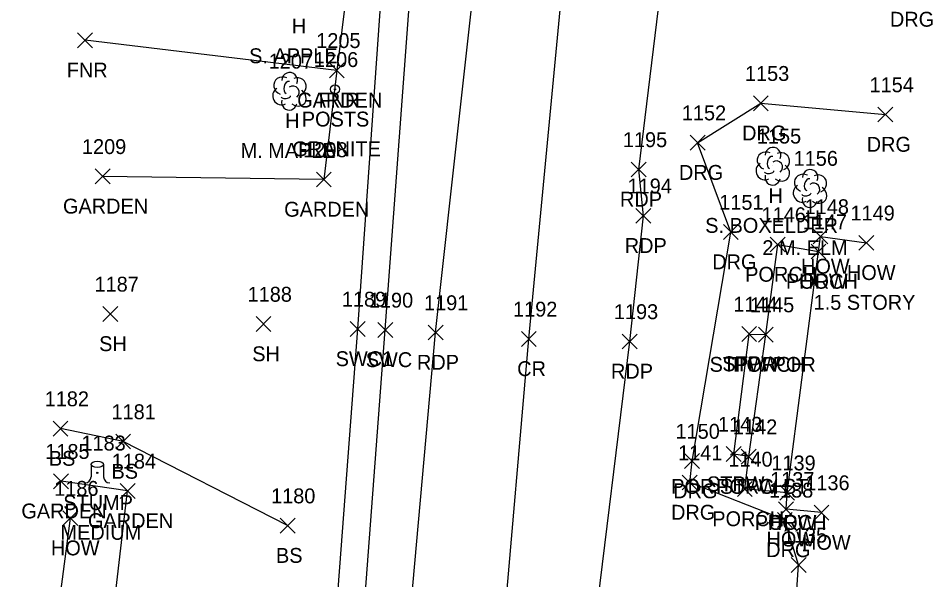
# Model space of a CAD drawing. Extents: x 1653908 to 1654393, y 539913 to 544256.
# Drawn here: x 1653960.4 to 1654083.2, y 541216.3 to 541291.8 of the extents above; entities that cross this region are included whole.
import ezdxf

# ---------------------------------------------------------------- set-up
doc = ezdxf.new("R2010")
doc.units = 0
for name, color, linetype in [('L_A', 7, 'Continuous'), ('L_C', 7, 'Continuous'), ('L_I', 7, 'Continuous'), ('L_TIC', 7, 'Continuous'), ('LAPB', 7, 'Continuous'), ('LBC', 7, 'Continuous'), ('LBF', 7, 'Continuous'), ('LELB', 7, 'Continuous'), ('LFNC', 7, 'Continuous'), ('LPST', 7, 'Continuous'), ('LTD', 7, 'Continuous'), ('LTS', 7, 'Continuous'), ('P_A', 7, 'Continuous'), ('P_I', 7, 'Continuous'), ('P_TIC', 7, 'Continuous'), ('PET', 7, 'Continuous'), ('PRC', 7, 'Continuous'), ('R_A', 7, 'Continuous'), ('R_I', 7, 'Continuous'), ('R_TIC', 7, 'Continuous'), ('RDG', 7, 'Continuous'), ('RSW', 7, 'Continuous')]:
    doc.layers.add(name, color=color, linetype=linetype)

msp = doc.modelspace()

# ---------------------------------------------------------------- linework, layer by layer
at = {"layer": 'L_TIC'}
for points in [[(1653968.35, 541287.8), (1653970.35, 541289.8)], [(1653970.35, 541287.8), (1653968.35, 541289.8)], [(1654002.18, 541283.76), (1654004.18, 541285.76)], [(1654004.18, 541283.76), (1654002.18, 541285.76)], [(1654002.18, 541283.76), (1654004.18, 541285.76)], [(1654004.18, 541283.76), (1654002.18, 541285.76)], [(1653970.71, 541269.51), (1653972.71, 541271.51)], [(1653972.71, 541269.51), (1653970.71, 541271.51)], [(1654000.43, 541269.09), (1654002.43, 541271.09)], [(1654002.43, 541269.09), (1654000.43, 541271.09)], [(1654061.42, 541260.35), (1654063.42, 541262.35)], [(1654063.42, 541260.35), (1654061.42, 541262.35)], [(1654067.16, 541261.43), (1654069.16, 541263.43)], [(1654069.16, 541261.43), (1654067.16, 541263.43)], [(1654073.32, 541260.58), (1654075.32, 541262.58)], [(1654075.32, 541260.58), (1654073.32, 541262.58)], [(1654066.9, 541259.41), (1654068.9, 541261.41)], [(1654068.9, 541259.41), (1654066.9, 541261.41)], [(1654066.9, 541259.41), (1654068.9, 541261.41)], [(1654068.9, 541259.41), (1654066.9, 541261.41)], [(1653971.75, 541251.02), (1653973.75, 541253.02)], [(1653973.75, 541251.02), (1653971.75, 541253.02)], [(1653992.32, 541249.66), (1653994.32, 541251.66)], [(1653994.32, 541249.66), (1653992.32, 541251.66)], [(1654057.57, 541248.32), (1654059.57, 541250.32)], [(1654059.57, 541248.32), (1654057.57, 541250.32)], [(1654059.81, 541248.24), (1654061.81, 541250.24)], [(1654061.81, 541248.24), (1654059.81, 541250.24)], [(1654059.81, 541248.24), (1654061.81, 541250.24)], [(1654061.81, 541248.24), (1654059.81, 541250.24)], [(1653965.04, 541235.61), (1653967.04, 541237.61)], [(1653967.04, 541235.61), (1653965.04, 541237.61)], [(1653973.46, 541233.87), (1653975.46, 541235.87)], [(1653975.46, 541233.87), (1653973.46, 541235.87)], [(1654055.5, 541232.18), (1654057.5, 541234.18)], [(1654057.5, 541232.18), (1654055.5, 541234.18)], [(1654057.52, 541231.84), (1654059.52, 541233.84)], [(1654059.52, 541231.84), (1654057.52, 541233.84)], [(1654057.52, 541231.84), (1654059.52, 541233.84)], [(1654059.52, 541231.84), (1654057.52, 541233.84)], [(1653965.12, 541228.53), (1653967.12, 541230.53)], [(1653967.12, 541228.53), (1653965.12, 541230.53)], [(1653974.07, 541227.23), (1653976.07, 541229.23)], [(1653976.07, 541227.23), (1653974.07, 541229.23)], [(1654056.99, 541227.49), (1654058.99, 541229.49)], [(1654058.99, 541227.49), (1654056.99, 541229.49)], [(1654062.69, 541226.99), (1654064.69, 541228.99)], [(1654064.69, 541226.99), (1654062.69, 541228.99)], [(1654062.69, 541226.99), (1654064.69, 541228.99)], [(1654064.69, 541226.99), (1654062.69, 541228.99)], [(1654062.53, 541224.76), (1654064.53, 541226.76)], [(1654064.53, 541224.76), (1654062.53, 541226.76)], [(1653966.38, 541223.57), (1653968.38, 541225.57)], [(1653968.38, 541223.57), (1653966.38, 541225.57)], [(1654067.3, 541224.32), (1654069.3, 541226.32)], [(1654069.3, 541224.32), (1654067.3, 541226.32)], [(1653995.56, 541222.56), (1653997.56, 541224.56)], [(1653997.56, 541222.56), (1653995.56, 541224.56)]]:
    msp.add_lwpolyline(points, dxfattribs=at)
at = {"layer": 'LAPB'}
for points in [[(1654003.18, 541284.76), (1654001.43, 541270.09), (1653971.71, 541270.51)], [(1653972.26, 541204.38), (1653975.07, 541228.23), (1653966.12, 541229.53)]]:
    msp.add_lwpolyline(points, dxfattribs=at)
at = {"layer": 'LBC'}
for points in [[(1654068.3, 541225.32), (1654063.53, 541225.76), (1654063.69, 541227.99), (1654067.9, 541260.41), (1654068.16, 541262.43), (1654074.32, 541261.58)], [(1653960.38, 541198.85), (1653963.61, 541198.2), (1653964.17, 541200.25), (1653965.17, 541207.51), (1653967.38, 541224.57)]]:
    msp.add_lwpolyline(points, dxfattribs=at)
at = {"layer": 'LBF'}
for points in [[(1654063.69, 541227.99), (1654057.99, 541228.49), (1654058.52, 541232.84), (1654060.81, 541249.24), (1654062.42, 541261.35), (1654067.9, 541260.41)], [(1654058.52, 541232.84), (1654056.5, 541233.18), (1654058.57, 541249.32), (1654060.81, 541249.24)]]:
    msp.add_lwpolyline(points, dxfattribs=at)
at = {"layer": 'LELB'}
msp.add_lwpolyline([(1653996.56, 541223.56), (1653974.46, 541234.87), (1653966.04, 541236.61)], dxfattribs=at)
at = {"layer": 'LFNC'}
msp.add_lwpolyline([(1654006.47, 541311.55), (1654003.18, 541284.76), (1653969.35, 541288.8)], dxfattribs=at)
at = {"layer": 'LPST'}
for radius in [0.625, 0.0833]:
    msp.add_circle((1654002.93, 541282.21), radius, dxfattribs=at)
at = {"layer": 'LTD'}
for p, q in [((1653996.79, 541282), (1653996.79, 541282)), ((1653996.79, 541282), (1653996.79, 541282)), ((1654061.74, 541271.92), (1654061.74, 541271.92)), ((1654061.74, 541271.92), (1654061.74, 541271.92)), ((1654066.73, 541268.93), (1654066.73, 541268.93)), ((1654066.73, 541268.93), (1654066.73, 541268.93))]:
    msp.add_line(p, q, dxfattribs=at)
for centre in [(1653996.84, 541283.43), (1654061.78, 541273.36), (1654066.78, 541270.37)]:
    msp.add_arc(centre, 1.05, 335.5272, 180.9563, dxfattribs=at)
for centre, major_axis, ratio, start_param, end_param in [((1653996, 541282.66), (1.21, -0.51), 0.895232, 1.570796, 4.712389), ((1653996.59, 541282.46), (-0.208, -0.792), 0.645439, 3.141593, 6.283185), ((1653997.84, 541282.58), (-1.14, -0.48), 0.949671, 1.570796, 4.712389), ((1653995.71, 541281.29), (0.58, -1.04), 0.959034, 3.141593, 6.283185), ((1653997.29, 541281.83), (-0.5, 0.667), 0.989748, 3.141593, 6.283185), ((1653997.79, 541281.16), (-1.09, 0.79), 0.841452, 1.570796, 4.712389), ((1653996.34, 541281.25), (-0.625, -0.083), 0.423636, 0, 3.141593), ((1653996.79, 541280.5), (0.26, 1.06), 0.942809, 1.570796, 4.712389), ((1654060.95, 541272.59), (1.21, -0.51), 0.895232, 1.570796, 4.712389), ((1654062.78, 541272.51), (-1.14, -0.48), 0.949671, 1.570796, 4.712389), ((1654060.65, 541271.22), (0.58, -1.04), 0.959034, 3.141593, 6.283185), ((1654061.53, 541272.38), (-0.208, -0.792), 0.645439, 3.141593, 6.283185), ((1654062.24, 541271.76), (-0.5, 0.667), 0.989748, 3.141593, 6.283185), ((1654061.28, 541271.17), (-0.625, -0.083), 0.423636, 0, 3.141593), ((1654062.74, 541271.09), (-1.09, 0.79), 0.841452, 1.570796, 4.712389), ((1654065.94, 541269.6), (1.21, -0.51), 0.895232, 1.570796, 4.712389), ((1654061.74, 541270.42), (0.26, 1.06), 0.942809, 1.570796, 4.712389), ((1654066.52, 541269.39), (-0.208, -0.792), 0.645439, 3.141593, 6.283185), ((1654067.23, 541268.77), (-0.5, 0.667), 0.989748, 3.141593, 6.283185), ((1654067.77, 541269.52), (-1.14, -0.48), 0.949671, 1.570796, 4.712389), ((1654065.65, 541268.23), (0.58, -1.04), 0.959034, 3.141593, 6.283185), ((1654067.73, 541268.1), (-1.09, 0.79), 0.841452, 1.570796, 4.712389), ((1654066.73, 541267.43), (0.26, 1.06), 0.942809, 1.570796, 4.712389), ((1654066.27, 541268.18), (-0.625, -0.083), 0.423636, 0, 3.141593)]:
    msp.add_ellipse(centre, major_axis=major_axis, ratio=ratio, start_param=start_param, end_param=end_param, dxfattribs=at)
at = {"layer": 'LTS'}
for p, q in [((1653970.16, 541231.8), (1653970.16, 541230.13)), ((1653971.83, 541231.63), (1653971.83, 541231.8)), ((1653971.83, 541231.8), (1653971.83, 541230.13)), ((1653970.99, 541230.66), (1653970.99, 541230.66)), ((1653970.99, 541230.66), (1653970.99, 541230.66)), ((1653970.99, 541230.63), (1653970.99, 541230.63))]:
    msp.add_line(p, q, dxfattribs=at)
msp.add_circle((1653970.99, 541230.66), 0.0833, dxfattribs=at)
for centre, start, end in [((1653969.33, 541230.13), 270, 360), ((1653972.66, 541230.13), 180, 270)]:
    msp.add_arc(centre, 0.833, start, end, dxfattribs=at)
msp.add_ellipse((1653970.99, 541231.8), major_axis=(-0.833, 0), ratio=0.5, dxfattribs=at)
at = {"layer": 'P_TIC'}
for points in [[(1654042.73, 541270.44), (1654044.73, 541272.44)], [(1654044.73, 541270.44), (1654042.73, 541272.44)], [(1654043.37, 541264.21), (1654045.37, 541266.21)], [(1654045.37, 541264.21), (1654043.37, 541266.21)], [(1654015.45, 541248.52), (1654017.45, 541250.52)], [(1654017.45, 541248.52), (1654015.45, 541250.52)], [(1654027.97, 541247.66), (1654029.97, 541249.66)], [(1654029.97, 541247.66), (1654027.97, 541249.66)], [(1654041.53, 541247.32), (1654043.53, 541249.32)], [(1654043.53, 541247.32), (1654041.53, 541249.32)]]:
    msp.add_lwpolyline(points, dxfattribs=at)
at = {"layer": 'PET'}
for points in [[(1654002.71, 541022.85), (1654002.8, 541044.57), (1654003.39, 541071.89), (1654004.24, 541078.69), (1654006.74, 541130.14), (1654008.35, 541153.98), (1654010.07, 541183.44), (1654012.88, 541209.94), (1654016.45, 541249.52), (1654022.91, 541308.12), (1654024.64, 541328.52), (1654031.79, 541410), (1654035.81, 541442.82), (1654037.01, 541460.37), (1654040.04, 541491.49), (1654045.58, 541525.89), (1654049.59, 541568.11), (1654053.33, 541590.16), (1654054.27, 541598.35), (1654062.59, 541587.52), (1654071.87, 541577.06), (1654070.19, 541559.91), (1654067.66, 541531.5), (1654064.32, 541497.28)], [(1654026.62, 541021.77), (1654028.54, 541070.24), (1654031.49, 541127.98), (1654037.66, 541208.54), (1654042.53, 541248.32), (1654044.37, 541265.21), (1654043.73, 541271.44), (1654047, 541298.33), (1654052.52, 541346.47), (1654054.45, 541365.83), (1654058.25, 541433.29), (1654064.32, 541497.28)]]:
    msp.add_lwpolyline(points, dxfattribs=at)
at = {"layer": 'PRC'}
msp.add_lwpolyline([(1654015.22, 541022.42), (1654016.68, 541078.09), (1654019.78, 541129.03), (1654023.08, 541180.04), (1654025.54, 541208.79), (1654028.97, 541248.66), (1654033.81, 541299.54), (1654044.55, 541409.64), (1654048.4, 541449.61), (1654049.07, 541458.74), (1654052.54, 541493.4), (1654055.94, 541523.17), (1654060.18, 541564.47), (1654062.59, 541587.52)], dxfattribs=at)
at = {"layer": 'R_TIC'}
for points in [[(1654059.14, 541279.34), (1654061.14, 541281.34)], [(1654061.14, 541279.34), (1654059.14, 541281.34)], [(1654075.88, 541277.82), (1654077.88, 541279.82)], [(1654077.88, 541277.82), (1654075.88, 541279.82)], [(1654050.65, 541274.04), (1654052.65, 541276.04)], [(1654052.65, 541274.04), (1654050.65, 541276.04)], [(1654055.12, 541262.02), (1654057.12, 541264.02)], [(1654057.12, 541262.02), (1654055.12, 541264.02)], [(1654004.98, 541249), (1654006.98, 541251)], [(1654006.98, 541249), (1654004.98, 541251)], [(1654008.69, 541248.87), (1654010.69, 541250.87)], [(1654010.69, 541248.87), (1654008.69, 541250.87)], [(1654049.9, 541231.24), (1654051.9, 541233.24)], [(1654051.9, 541231.24), (1654049.9, 541233.24)], [(1654049.59, 541228.36), (1654051.59, 541230.36)], [(1654051.59, 541228.36), (1654049.59, 541230.36)], [(1654062.37, 541223.33), (1654064.37, 541225.33)], [(1654064.37, 541223.33), (1654062.37, 541225.33)], [(1654064.22, 541217.28), (1654066.22, 541219.28)], [(1654066.22, 541217.28), (1654064.22, 541219.28)]]:
    msp.add_lwpolyline(points, dxfattribs=at)
at = {"layer": 'RDG'}
msp.add_lwpolyline([(1654028.54, 541070.24), (1654038.6, 541077.25), (1654059.57, 541076.94), (1654061.03, 541094.58), (1654044.02, 541099.01), (1654043.13, 541126.19), (1654037.88, 541140.53), (1654039.43, 541148.38), (1654055.52, 541147.43), (1654059.02, 541158.08), (1654052.9, 541167.53), (1654052.51, 541181.31), (1654043.29, 541183.51), (1654044.31, 541207.87), (1654064.52, 541208.31), (1654065.22, 541218.28), (1654063.37, 541224.33), (1654050.59, 541229.36), (1654050.9, 541232.24), (1654056.12, 541263.02), (1654051.65, 541275.04), (1654060.14, 541280.34), (1654076.88, 541278.82)], dxfattribs=at)
at = {"layer": 'RSW'}
for points in [[(1653995.61, 541066.36), (1653991.56, 541066.06), (1653992.58, 541078.58), (1653996.53, 541130.67), (1653999, 541158.35), (1654000.18, 541180.99), (1654002.98, 541210.26), (1654005.98, 541250), (1654010.23, 541310.58)], [(1653995.61, 541066.36), (1653996.52, 541078.59), (1654000.45, 541130.29), (1654004.36, 541181.55), (1654006.66, 541209.97), (1654009.69, 541249.87), (1654014.15, 541310.29), (1654010.23, 541310.58)]]:
    msp.add_lwpolyline(points, dxfattribs=at)

# ---------------------------------------------------------------- texts
at = {"layer": 'L_A'}
for s, p in [('H', (1653997.12, 541289.72)), ('FNR', (1653966.89, 541283.8)), ('GARDEN', (1653997.85, 541279.76)), ('FNR', (1654000.72, 541279.76)), ('H', (1653996.23, 541277)), ('POSTS', (1653998.47, 541277.21)), ('H', (1654061.17, 541266.92)), ('GARDEN', (1653966.38, 541265.51)), ('GARDEN', (1653996.1, 541265.09)), ('H', (1654066.16, 541263.93)), ('HOW', (1654065.54, 541257.43)), ('PORCH', (1654058.04, 541256.35)), ('PORCH', (1654063.52, 541255.41)), ('HOW', (1654065.28, 541255.41)), ('HOW', (1654071.71, 541256.58)), ('SH', (1653971.24, 541247.02)), ('SH', (1653991.81, 541245.66)), ('STPW POR', (1654053.26, 541244.24)), ('STPW', (1654054.97, 541244.32)), ('PORCH', (1654056.43, 541244.24)), ('BS', (1653964.48, 541231.61)), ('BS', (1653972.9, 541229.87)), ('POR STPW ST', (1654048.1, 541227.84)), ('STPW', (1654052.9, 541228.18)), ('PORCH', (1654054.14, 541227.84)), ('STUMP', (1653966.42, 541225.66)), ('GARDEN', (1653960.79, 541224.53)), ('PORCH', (1654053.62, 541223.49)), ('GARDEN', (1653969.74, 541223.23)), ('PORCH', (1654059.32, 541222.99)), ('HOW', (1654061.08, 541222.99)), ('HOW', (1654060.91, 541220.76)), ('HOW', (1654065.68, 541220.32)), ('HOW', (1653964.76, 541219.57)), ('BS', (1653995, 541218.56))]:
    msp.add_text(s, height=2, dxfattribs=at).set_placement(p)
at = {"layer": 'L_C'}
for s, p in [('S. APPLE', (1653991.39, 541285.72)), ('M. MAPLE', (1653990.24, 541273)), ('GRANITE', (1653997.2, 541273.21)), ('S. BOXELDER', (1654052.67, 541262.92)), ('2 M. ELM', (1654060.35, 541259.93)), ('1.5 STORY', (1654067.24, 541252.58)), ('MEDIUM', (1653966.05, 541221.66))]:
    msp.add_text(s, height=2, dxfattribs=at).set_placement(p)
at = {"layer": 'L_I'}
for s, p in [('1205', (1654000.41, 541287.76)), ('1205', (1654000.41, 541287.76)), ('1207', (1653994.02, 541285)), ('1206', (1654000.1, 541285.21)), ('1155', (1654059.61, 541274.92)), ('1209', (1653968.93, 541273.51)), ('1208', (1653998.66, 541273.09)), ('1156', (1654064.55, 541271.93)), ('1148', (1654066.03, 541265.43)), ('1146', (1654060.24, 541264.35)), ('1149', (1654072.19, 541264.58)), ('1147', (1654065.77, 541263.41)), ('1147', (1654065.77, 541263.41)), ('1187', (1653970.62, 541255.02)), ('1188', (1653991.19, 541253.66)), ('1144', (1654056.45, 541252.32)), ('1145', (1654058.68, 541252.24)), ('1145', (1654058.68, 541252.24)), ('1182', (1653963.92, 541239.61)), ('1181', (1653972.9, 541237.87)), ('1143', (1654054.38, 541236.18)), ('1142', (1654056.4, 541235.84)), ('1142', (1654056.4, 541235.84)), ('1183', (1653968.86, 541233.66)), ('1185', (1653964, 541232.53)), ('1184', (1653972.94, 541231.23)), ('1140', (1654055.78, 541231.49)), ('1139', (1654061.56, 541230.99)), ('1139', (1654061.56, 541230.99)), ('1137', (1654061.4, 541228.76)), ('1186', (1653965.2, 541227.57)), ('1136', (1654066.12, 541228.32)), ('1180', (1653994.34, 541226.56))]:
    msp.add_text(s, height=2, dxfattribs=at).set_placement(p)
at = {"layer": 'P_A'}
for s, p in [('RDP', (1654041.22, 541266.44)), ('RDP', (1654041.86, 541260.21)), ('RDP', (1654013.94, 541244.52)), ('CR', (1654027.41, 541243.66)), ('RDP', (1654040.01, 541243.32))]:
    msp.add_text(s, height=2, dxfattribs=at).set_placement(p)
at = {"layer": 'P_I'}
for s, p in [('1195', (1654041.61, 541274.44)), ('1194', (1654042.24, 541268.21)), ('1191', (1654014.89, 541252.52)), ('1192', (1654026.85, 541251.66)), ('1193', (1654040.4, 541251.32))]:
    msp.add_text(s, height=2, dxfattribs=at).set_placement(p)
at = {"layer": 'R_A'}
for s, p in [('DRG', (1654077.49, 541290.63)), ('DRG', (1654057.63, 541275.34)), ('DRG', (1654074.37, 541273.82)), ('DRG', (1654049.14, 541270.04)), ('DRG', (1654053.61, 541258.02)), ('SWC1', (1654003.02, 541245)), ('SWC', (1654007.06, 541244.87)), ('DRG', (1654048.38, 541227.24)), ('DRG', (1654048.08, 541224.36)), ('DRG', (1654060.86, 541219.33))]:
    msp.add_text(s, height=2, dxfattribs=at).set_placement(p)
at = {"layer": 'R_I'}
for s, p in [('1153', (1654058.01, 541283.34)), ('1154', (1654074.75, 541281.82)), ('1152', (1654049.53, 541278.04)), ('1151', (1654054.56, 541266.02)), ('1189', (1654003.85, 541253)), ('1190', (1654007.48, 541252.87)), ('1150', (1654048.68, 541235.24)), ('1141', (1654049.03, 541232.36)), ('1138', (1654061.24, 541227.33)), ('1135', (1654063.1, 541221.28))]:
    msp.add_text(s, height=2, dxfattribs=at).set_placement(p)

doc.saveas('drawing.dxf')
